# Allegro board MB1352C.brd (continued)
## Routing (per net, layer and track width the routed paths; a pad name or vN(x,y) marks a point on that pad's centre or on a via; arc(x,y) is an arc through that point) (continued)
NETCN4_3: length 38.4
  BOTTOM w0.155: SB63.1 41.96,44.78 41.96,47.77 31.87,57.86 18.19,57.86 17.6,57.28 16.38,57.28 15.57,58.09 15.57,59.72 16,60.15 16.49,60.15 CN4.3
NETCN6_13: length 14.6
  TOP w0.127: v1(10.79,38.86) 11.03,39.1 CN6.13 ; R20.2 v2(19.56,43.43)
  L3_SIG w0.102: v1(10.79,38.86) 11.1,39.17 12.14,39.17 16.92,43.94 19.05,43.94 v2(19.56,43.43)
NETCN6_14: length 14.6
  TOP w0.127: v1(10.79,39.88) 11.07,39.6 CN6.14 ; R15.2 v2(19.56,44.7)
  L3_SIG w0.102: v2(19.56,44.7) 19.18,44.32 16.76,44.32 11.98,39.55 11.13,39.55 v1(10.79,39.88)
NETCN6_19: length 3.9
  TOP w0.127: CN6.19 15.43,42.1 SB6.1
NETCN8_17: length 7
  BOTTOM w0.508: SB59.1 97.03,11.68 97.03,8.64 CN8.17
NETCN9_15: length 10
  BOTTOM w0.203: U7.1 44.2,11.05 SB24.2
  BOTTOM w0.508: SB24.2 43.81,11.68 42.55,12.95 36.83,12.95 CN9.15
NETD3_2: length 13.1
  BOTTOM w0.381: T10.3 28.63,10.85 ; T10.2 29.28,10.85
  BOTTOM w0.508: D8.2 29.88,8.89 ; D8.2 28.7,9.91 ; D8.2 28.7,7.87 ; 30.31,11.64 T10.1 29.93,10.97 ; 32.51,8.98 D3.2 ; D3.2 33.53,10.17 ; D3.2 31.5,10.17 ; D3.2 32.51,11.35 ; JP5.1 52.68,10.36 ; JP5.1 51.74,9.42 ; JP5.1 50.8,10.36
NETD7_2: length 18
  TOP w0.508: 106.17,14.61 U21.1 106.66,13.62 ; D7.2 112.07,15.75 ; D7.2 110.24,17.07 ; D7.2 108.41,15.75 ; D7.2 110.24,14.43 ; 104.3,20.82 L4.1 ; L4.1 110.17,20.82 ; L4.1 107.24,18.65 ; L4.1 107.24,23
NETD9_2: length 18.9
  TOP w0.508: 70.74,7.75 71.25,8.26 U22.1 ; D9.2 73.58,4.19 ; D9.2 72.26,2.36 ; D9.2 70.94,4.19 ; D9.2 72.26,6.02 ; L5.1 78.23,10.05 ; L5.1 78.23,4.18 ; L5.1 80.4,7.11 ; L5.1 76.05,7.11 ; 71.41,7.77 U22.1 ; U22.1 72.4,8.26
NETD11_1: length 2.1
  BOTTOM w0.127: D11.1 86.58,29.99 86.88,30.29 U10.1
NETD12_1: length 2
  TOP w0.127: D12.1 87.14,32.24 87.19,32.19 U14.1
NETLD1_1: length 1.5
  TOP w0.508: LD1.1 R125.1
NETLD2_1: length 1.5
  TOP w0.508: R10.1 LD2.1
NETR7_1: length 3.2
  TOP w0.508: R53.2 R54.2 R7.1
NETR7_2: length 5.5
  TOP w0.508: R7.2 89.28,20.6 88.65,21.23 v1(87.93,21.23)
  BOTTOM w0.508: v1(87.93,21.23) 87.93,19.13 88.39,18.67 SB3.2
NETR11_1: length 21.6
  TOP w0.127: 26.61,31.94 R36.2
  TOP w0.13: v2(23.04,46.25) 22.87,46.42 22.54,46.42 R11.1 ; U13.24 26.1,34.3 26.1,33.18 26.61,32.67 26.61,32.5 v2(26.44,32.33) 26.61,32.17 26.61,31.94
  BOTTOM w0.13: v2(23.04,46.25) 23.2,46.42 23.68,46.42 23.93,46.17 23.93,45.54 23.7,45.31 23.7,45.05 23.93,44.82 23.93,44.56 23.7,44.33 23.7,44.07 23.93,43.84 23.93,43.59 23.7,43.36 23.7,43.1 23.93,42.87 23.93,34.62 25.76,32.79 26.46,32.79 26.59,32.66 26.59,32.48 v2(26.44,32.33)
NETR12_1: length 21.7
  TOP w0.13: v2(23.04,46.96) 22.87,46.8 22.54,46.8 R12.1 ; R37.2 26.99,31.94 26.99,32.17 v2(27.15,32.33) 26.99,32.5 26.99,32.83 26.48,33.34 26.48,34.3 U13.25
  BOTTOM w0.13: v2(27.15,32.33) 26.97,32.51 26.97,32.82 26.62,33.17 25.91,33.17 24.31,34.78 24.31,46.33 23.84,46.8 23.2,46.8 v2(23.04,46.96)
NETR14_1: length 2.9
  TOP w0.127: U6.18 69.2,45.07 69.72,45.59 R14.1
NETR32_2: length 1.4
  BOTTOM w0.508: R75.1 R32.2
NETR33_2: length 9.1
  TOP w0.508: v1(92.84,31.11) 92.08,31.88 R34.2 91.51,32.19 U14.5 90.17,32.38 90.17,33.66 SB8.2 SB9.2
  BOTTOM w0.508: U10.5 91.76,30.29 R33.2 92.08,30.35 v1(92.84,31.11)
NETR41_1: length 1.2
  TOP w0.508: 31.88,27.51 R41.1 32.45,26.92
NETR43_2: length 2
  TOP w0.508: R43.2 v1(89.15,24.38)
  BOTTOM w0.508: v1(89.15,24.38) R43.2
NETR47_2: length 17.1
  TOP w0.508: R49.2 29.16,21.97 ; R49.2 27.79,21.97 ; R49.2 28.47,20.52 ; R49.2 28.47,23.42 ; 27.79,18.8 R56.2 ; R56.2 29.16,18.8 ; R56.2 28.47,20.24 ; R56.2 28.47,17.35 ; R47.2 28.47,17.07 ; R47.2 28.47,14.17 ; R47.2 29.16,15.62 ; R47.2 27.79,15.62 ; R52.2 29.16,12.45 ; R52.2 28.47,13.89 ; R52.2 28.47,11 ; R52.2 27.79,12.45
NETR48_2: length 17.1
  TOP w0.508: 44.5,28.7 R55.2 ; R55.2 45.87,28.7 ; R55.2 45.19,30.15 ; R55.2 45.19,27.25 ; R50.2 45.31,23.55 ; R50.2 44.63,22.1 ; R50.2 45.31,20.65 ; R50.2 46,22.1 ; 44.63,18.8 R48.2 ; R48.2 46,18.8 ; R48.2 45.31,20.24 ; R48.2 45.31,17.35 ; 45.19,23.95 R59.2 ; R59.2 45.19,26.85 ; R59.2 44.5,25.4 ; R59.2 45.87,25.4
NETR57_2: length 4
  TOP w0.381: R57.2 30.48,20.03 30.21,20.3 T8.3
  TOP w0.508: R57.2 30.61,19.18 30.61,17.65 30.23,17.27
NETR58_2: length 3.9
  TOP w0.508: v1(40.89,30.61) 40.51,30.23 R58.2 40.62,29.48 T9.3
  BOTTOM w0.508: SB36.2 40.44,30.15 v1(40.89,30.61)
NETR62_2: length 1.8
  TOP w0.508: U18.4 82.77,23.46 R62.2
NETR71_2: length 2.2
  TOP w0.508: R71.2 64.9,10.67 65.02,10.79 U22.6
NETR72_2: length 2.6
  BOTTOM w0.381: T10.4 27.98,11.9 27.69,12.19 27.18,12.19 26.29,13.08 26.16,13.08
NETR76_2: length 2.7
  TOP w0.508: R76.2 104.52,6.73 103.63,7.62 U21.6
NETR101_2: length 2.3
  TOP w0.508: U29.4 50.99,45.02 v1(50.93,44.96)
  BOTTOM w0.508: R101.2 50.93,44.32 v1(50.93,44.96)
NETR110_2: length 2.4
  TOP w0.508: v1(76.96,22.1) 76.96,22.35 77.22,22.61 U18.1
  BOTTOM w0.508: R110.2 76.96,22.86 v1(76.96,22.1)
NETR115_2: length 1.8
  BOTTOM w0.381: U27.4 51.45,25.71 51.27,25.53 R115.2
NETR116_2: length 4.7
  BOTTOM w0.508: U28.4 26.61,22.41 27.3,21.72 29.97,21.72 R116.2
NETR120_1: length 3.1
  BOTTOM w0.203: R120.1 SB24.1 44.81,9.91 U7.6
NETR121_1: length 27.7
  TOP w0.356: U24.1 43.67,9.54 43.46,9.75 42.93,9.75
  TOP w0.508: U26.1 v1(40.83,22.41) 40.64,22.61 38.99,22.61 37.72,21.34 35.69,21.34 34.92,20.57 34.92,11.94 35.81,11.05 37.47,11.05 38.77,9.75 42.93,9.75
  BOTTOM w0.508: R121.1 40.83,23.43 v1(40.83,22.41)
NETR121_2: length 2.5
  TOP w0.508: v1(42.55,22.48) 42.73,22.67 U26.4
  BOTTOM w0.508: R121.2 v1(42.55,22.48)
NETR122_1: length 17.2
  TOP w0.381: v1(21.08,2.54) 21.45,2.91 U23.1
  TOP w0.508: U25.1 19.37,15.05 v1(19.37,15.05)
  BOTTOM w0.508: v1(21.08,2.54) 20.83,2.54 18.67,4.7 18.67,14.35 v1(19.37,15.05) 19.81,15.49 R122.1
NETR122_2: length 2.6
  TOP w0.508: U25.4 21.27,15.94 21.72,15.49 v1(21.72,15.11)
  BOTTOM w0.508: R122.2 21.72,15.62 v1(21.72,15.11)
NETR126_1: length 2.6
  TOP w0.508: R126.1 16.03,9.93 16.38,10.29 SB25.1
NETSB7_2: length 3.6
  TOP w0.127: SB7.2 70.61,41.78 70.1,42.29 70.1,42.67 69.21,43.57 U6.15
NETSB10_2: length 4.3
  TOP w0.127: SB10.2 69.72,41.53 69.72,42.42 69.07,43.07 U6.14
NETSB11_2: length 1.5
  TOP w0.508: SB11.2 93.3,35.6 T3.1
NETSB12_2: length 1.8
  TOP w0.508: SB12.2 90.3,35.96 T2.1
NETSB16_2: length 3.3
  TOP w0.203: U16.7 96.75,55.39 v1(96.52,55.63) 96.39,55.75 SB16.2
  BOTTOM w0.203: v1(96.52,55.63) 96.39,55.75 SB16.2
NETSB17_2: length 4.1
  TOP w0.203: U16.6 97.28,55.79 v1(96.5,56.57) 95.67,57.4 SB17.2
  BOTTOM w0.203: SB17.2 95.67,57.4 v1(96.5,56.57)
NETSB18_1: length 4.5
  TOP w0.127: U13.21 24.89,33.78 24.07,32.96 23.43,32.96 22.99,32.51 22.99,32.26 SB18.1
NETSB19_1: length 3.7
  TOP w0.127: U13.22 25.29,33.42 24.26,32.39 24.26,32.13 SB19.1
NETSB20_1: length 3.3
  TOP w0.127: U13.23 25.69,33.06 24.89,32.26 SB20.1
NETSB21_1: length 2.1
  TOP w0.127: SB21.1 16.28,26.27 U17.12
NETSB22_1: length 2.2
  TOP w0.127: U17.11 16.68,26.2 SB22.1
NETSB26_2: length 14.6
  TOP w0.508: U18.3 79.76,22.61 81.41,20.95 84.45,20.95 85.72,22.23 90.04,22.23 v1(90.3,21.97)
  BOTTOM w0.508: SB26.2 90.32,20.55 90.32,21.95 v1(90.3,21.97)
NETSB27_2: length 3.7
  TOP w0.127: U17.6 17.66,22.57 v1(18.27,21.96) 18.51,21.72 SB27.2
  BOTTOM w0.127: v1(18.27,21.96) 18.51,21.72 SB27.2
NETSB28_2: length 3.6
  TOP w0.127: U17.7 17.8,22.97 18.03,22.73 v1(18.29,22.73) 18.67,23.11 SB28.2
  BOTTOM w0.127: v1(18.29,22.73) 18.67,23.11 SB28.2
NETSB33_2: length 2.7
  TOP w0.508: U21.3 103.63,14.13 105.16,15.65
NETSB37_2: length 2.1
  TOP w0.508: U22.3 72.26,10.79 72.9,10.16 SB37.2
NETSB48_1: length 4.7
  TOP w0.127: U13.32 28.81,36.21 29.72,35.31 29.72,35.18 v1(30.42,34.48)
  BOTTOM w0.127: 30.1,33.27 29.91,33.46 29.91,34.23 30.16,34.48 v1(30.42,34.48)
NETSB51_1: length 3.6
  TOP w0.127: U16.11 98.26,52.96 97.62,52.32 SB51.1
NETSB52_1: length 4.9
  TOP w0.127: U16.12 98.66,52.58 96.75,50.67 SB52.1
NETSB68_2: length 1.7
  TOP w0.155: SB68.2 101.43,55.79 U16.20
NETSB69_2: length 1.7
  TOP w0.155: SB69.2 101.43,55.39 U16.19
NETSB70_2: length 3.7
  TOP w0.155: U17.20 14.36,22.59 13.71,22.59 13.26,23.04 13.26,24 13.08,24.18 12.78,24.18 SB70.2
NETSB71_2: length 3.7
  TOP w0.155: SB71.2 12.8,24.56 13.23,24.56 13.64,24.16 13.64,23.2 13.87,22.97 U17.19
NETTP6_1: length 6.7
  TOP w0.127: U13.29 28.19,34.55 29.46,33.27 29.46,32.77 30.1,32.13 30.48,32.13 31.88,30.73 TP6.1
PORT1_CC1: length 62.2
  TOP w0.508: CN8.1 95.38,45.09 90.55,45.09 90.36,44.9 D10.1 90.36,42.87 89.92,42.42 SB4.1 89.92,39.35 T2.2 v1(88.27,38.8)
  BOTTOM w0.508: v1(88.27,38.8) 89.53,40.07 89.53,41.53 77.09,53.98 77.09,66.42 78.61,67.94 86.36,67.94 JP2.1
PORT1_CC2: length 49.2
  TOP w0.508: v1(91.95,38.8) T3.2 93.3,40.3 SB5.1 93.09,42.04 92.2,42.93 92.2,43.82 D10.3 92.45,44.07 96.9,44.07 CN8.2
  BOTTOM w0.508: JP1.1 79.5,66.42 78.36,65.28 78.36,54.36 83.44,49.28 85.6,49.28 90.55,44.32 90.55,40.19 v1(91.95,38.8)
PORT1_DB1: length 27.9
  BOTTOM w0.508: CN8.3 96.65,44.58 96.65,50.04 94.23,52.45 92.33,52.45 88.01,56.77 88.01,58.55 86.11,60.45 86.11,62.1 87.88,63.88
PORT1_DB2: length 32.8
  BOTTOM w0.508: 80.14,63.88 81.28,63.88 87,58.17 87,56.39 91.82,51.56 93.73,51.56 95.76,49.53 95.76,42.93 CN8.4
PORT2_CC1: length 53.4
  TOP w0.127: SB52.2 v1(93.09,49.78) 92.26,48.96 D10.4
  L3_SIG w0.102: v1(99.95,42.67) 101.55,41.07 102.9,41.07 103.3,40.67 103.3,37.39 99.85,33.93 99.85,19.08 CN8.13
  BOTTOM w0.127: SB44.2 100.46,43.18 v1(99.95,42.67) 99.31,42.04 99.31,39.75 98.93,39.37 97.06,39.37 94.61,41.81 94.61,48.26 v1(93.09,49.78)
PORT2_CC2: length 60.4
  TOP w0.127: D10.6 90.36,47.82 v1(92.33,49.78) 93.22,50.67 93.22,51.56 SB51.2
  L3_SIG w0.102: CN8.14 100.2,16.89 100.2,33.78 103.66,37.24 103.66,40.82 103.05,41.43 101.7,41.43 100.97,42.16 v1(100.97,42.54)
  BOTTOM w0.127: v1(92.33,49.78) 92.33,49.53 94.23,47.62 94.23,41.66 97.03,38.86 99.06,38.86 99.69,39.5 99.69,41.78 100.08,42.16 100.6,42.16 v1(100.97,42.54) 101.85,43.42 SB45.2
PSU: length 64
  TOP w0.508: 54.36,56.08 TP2.1 ; TP2.1 53.42,57.02 ; TP2.1 55.3,57.02 ; TP2.1 54.36,57.96 ; 107.62,1.98 C71.1 ; C71.1 106.86,3.43 ; C71.1 107.62,4.88 ; C71.1 108.38,3.43 ; SB33.1 v1(106.17,17.4) ; 77.98,15.54 C106.1 ; C106.1 77.98,16.71 ; C106.1 78.6,16.13 ; C107.1 78.6,17.53 ; C107.1 77.98,16.94 ; C107.1 77.98,18.11 ; 106.17,7.23 U21.8 106.66,8.22 ; 78,23.46 U18.2 ; U18.2 78.97,23.46 ; U18.2 78.49,21.97 ; C59.1 78.11,21.54 ; C59.1 78.73,20.95 ; C59.1 78.11,20.37 ; 80.06,18.41 R3.2 ; R3.2 81.23,18.41 ; R3.2 80.64,17.84 ; R125.2 47.62,57.91 ; C105.1 78.85,19.3 ; C105.1 78.11,20.12 ; C105.1 78.11,18.49 ; 49.91,53.72 52.63,53.72 ; 49.91,53.72 49.91,52.02 ; 49.91,53.72 49.91,55.42 ; L1.3 52.69,63.16 ; L1.3 51.52,61.99 ; L1.3 51.52,64.33 ; L1.3 50.35,63.16 ; 107.7,5.38 C65.1 ; C65.1 107.7,6.55 ; C65.1 107.07,5.97
  BOTTOM w0.508: 26.16,10.98 R72.1 ; R72.1 25.58,11.56 ; R72.1 26.75,11.56 ; v1(106.43,3.68) 106.43,17.14 v1(106.17,17.4) ; 24.18,11.56 R73.2 ; R73.2 25.35,11.56 ; R73.2 24.77,10.98 ; 24.9,7.87 D8.1 ; D8.1 23.72,8.89 ; D8.1 24.9,9.91 ; D8.1 26.08,8.89
  vias: v1(25.68,5.84) v1(25.65,5.08) v1(26.42,5.84) v1(26.42,5.08) v1(53.47,55.24) v1(53.47,54.36) v1(54.23,55.24) v1(54.23,54.36) v1(54.99,55.24) v1(54.99,54.36) v1(79.38,16.89) v1(79.38,16.13) v1(79.38,15.24) v1(80.14,16.89) v1(80.14,16.13) v1(80.14,15.24) v1(105.66,3.68) v1(105.66,2.79) v1(105.66,2.03) v1(106.43,2.79) v1(106.43,2.03)
PWD#: length 29
  TOP w0.127: U6.37 60.85,43.07 59.69,41.91 59.69,41.53 R25.1 v1(58.67,39.5)
  L3_SIG w0.102: CN9.6 40.01,38.99 57.4,38.99 57.91,39.5 v1(58.67,39.5)
PWM_CTL: length 4.6
  TOP w0.508: R61.1 R51.1 94.23,20.19 v1(95,19.43)
  BOTTOM w0.508: SB2.2 94.23,18.67 v1(95,19.43)
SOURCE_EN: length 65.3
  TOP w0.127: R124.2 54.61,37.85 v1(58.93,33.53)
  TOP w0.254: T5.3 49.04,37.48 R124.2
  L3_SIG w0.102: v1(58.93,33.53) 59.69,32.77 82.55,32.77 85.22,30.1 85.22,27.46 88.93,23.75 88.93,18.72 90.88,16.76 93.09,16.76 97.41,12.45 CN8.15
SSEQ0_A0: length 4.6
  TOP w0.127: v1(22.91,40.01) 22.94,40.01 23.06,39.88 23.06,39.5 23.95,38.61 U13.11
  BOTTOM w0.127: R93.2 R95.1 22.73,40.01 v1(22.91,40.01)
SSEQ1: length 5.3
  TOP w0.127: R19.1 28.57,42.67 28.57,42.42 v1(28.38,42.23) 28.19,42.04 28.07,42.04 26.89,40.86 U13.3
  BOTTOM w0.127: v1(28.38,42.23) 28.57,42.42 28.57,42.67 R19.1
SSRX+: length 25.3
  TOP w0.155: C21.1 26.99,45.15 26.99,48.04 25.12,49.91 16.64,49.91 16.18,50.37 16.18,50.92 v1(15.96,51.14) 16.18,51.35 16.18,52.49 16.12,52.55 U4.4
  BOTTOM w0.155: CN4.6 18.94,55.98 18.94,55.16 16.18,52.41 16.18,51.35 v1(15.96,51.14)
SSRX-: length 25.3
  TOP w0.155: C22.1 27.37,45.15 27.37,48.2 25.27,50.29 16.79,50.29 16.56,50.53 16.56,50.92 v1(16.78,51.14) 16.56,51.35 16.56,52.49 16.62,52.55 U4.5
  BOTTOM w0.155: v1(16.78,51.14) 16.56,51.35 16.56,52.25 19.32,55.01 19.32,55.98 CN4.5
SSTX+: length 22.9
  TOP w0.155: U4.1 14.62,52.94 14.68,52.88 14.68,52.24 v1(14.46,52.03) 14.68,51.81 14.68,50.06 15.97,48.77 22.96,48.77 24.32,47.4 24.32,45.15 C19.1
  BOTTOM w0.155: v1(14.46,52.03) 14.68,52.24 14.68,52.85 12.19,55.35 12.19,55.98 CN4.9
SSTX-: length 22.9
  TOP w0.155: C20.1 24.7,45.15 24.7,47.56 23.11,49.15 16.13,49.15 15.06,50.22 15.06,51.81 v1(15.28,52.03) 15.06,52.24 15.06,52.91 15.12,52.97 U4.2
  BOTTOM w0.155: v1(15.28,52.03) 15.06,52.24 15.06,53.01 12.57,55.5 12.57,55.98 CN4.8
SW_EN: length 5.3
  TOP w0.127: R29.1 R28.2 82.92,36.71 U8.J5
USB3_DET: length 21.1
  TOP w0.508: R1.2 R2.1 32.26,56.39 34.54,54.1 34.54,47.24 CN9.2
V_CTL1: length 6.3
  BOTTOM w0.508: CN8.12 98.17,20.19 SB2.1 SB14.1
V_CTL2: length 74.5
  L3_SIG w0.102: v1(53.61,40.64) 53.48,40.51 50.04,40.51 49.15,41.4 48.13,41.4 47.36,40.62 40.91,40.62 37.47,44.07 37.47,46.86 CN9.1
  BOTTOM w0.127: SB23.1 SB15.1 91.19,22.86 91.19,25.02 91.06,25.15 87.5,25.15 84.2,28.45 84.2,32.1 83.54,32.77 71.85,32.77 69.82,34.8 58.9,34.8 53.61,40.09 v1(53.61,40.64)
VCONN_EN1: length 19.2
  TOP w0.508: SB12.1 v1(87.25,35.43) ; CN8.6 95.76,32.77 v1(93.85,32.77)
  L3_SIG w0.508: v1(87.25,35.43) 87.63,35.05 91.57,35.05 v1(93.85,32.77)
  BOTTOM w0.508: U10.4 91.51,32.19 R33.1 R9.1 v1(93.85,32.77)
VCONN_EN2: length 18.5
  TOP w0.508: v1(91.57,36.58) 91.95,36.2 SB11.1 ; U14.4 91.76,30.29 R34.1 R8.2 v1(94.74,30.35) 95.89,30.35 CN8.7
  L3_SIG w0.508: v1(94.74,30.35) 95.63,31.24 95.63,32.51 v1(91.57,36.58)
VCONN_OUT: length 90.6
  TOP w0.508: 109.8,33.15 TP5.1 ; TP5.1 110.74,34.09 ; TP5.1 111.68,33.15 ; TP5.1 110.74,32.21 ; SB9.1 94.49,33.78 94.74,34.04 v1(95.76,34.04) ; 105.54,34.14 C45.1 ; C45.1 106.3,35.59 ; C45.1 106.3,32.69 ; C45.1 107.06,34.14 ; L4.2 110.17,29.72 ; L4.2 104.3,29.72 ; L4.2 107.24,27.55 ; L4.2 107.24,31.9 ; v1(103.25,6.86) 103.12,6.73 C74.1
  BOTTOM w0.508: JP3.1 85.22,52.58 93.6,44.2 93.6,40.77 95.5,38.86 95.5,34.29 v1(95.76,34.04) 99.57,34.04 100.58,35.05 102.87,35.05 103.38,35.56 v1(105.16,35.56) 105.13,35.53 105.13,9.63 103.17,7.66 103.17,6.94 v1(103.25,6.86) 103.38,6.73 103.89,6.73 104.52,6.1 R75.2
VDC: length 30
  TOP w0.508: 58.37,7.19 C66.1 ; C66.1 61.27,7.19 ; C66.1 59.82,7.95 ; C66.1 59.82,6.43 ; v1(74.8,9.02) 74.8,10.03 ; C67.1 62.81,6.35 ; C67.1 61.65,6.35 ; C67.1 62.23,6.97 ; 65.02,8.26 U22.8 66.01,7.77
  BOTTOM w0.508: v1(74.8,9.02) 58.93,9.02 v1(57.78,7.87) ; JP5.2 52.68,12.9 ; JP5.2 51.74,11.96 ; JP5.2 50.8,12.9 ; JP5.2 51.74,13.84
  vias: v1(56.9,7.87) v1(56.9,6.99) v1(56.9,6.22) v1(57.78,6.99) v1(57.78,6.22)
VSENSE_1: length 11
  BOTTOM w0.508: U28.1 28.57,20.57 R116.1 31.62,20.57 32.89,21.84 32.89,24 34.04,25.15 CN9.10
VSENSE_2: length 21.7
  BOTTOM w0.508: CN9.12 39.75,23.5 39.75,24.13 40.26,24.64 46.74,24.64 47.37,24 R115.1 50.93,24 51.56,24.64 53.72,24.64 54.16,24.2 U27.1
VSENSE_DCDC: length 62.9
  TOP w0.127: U29.1 41.85,43.89 40.01,42.04 v1(40.01,37.97)
  TOP w0.508: U29.1 v1(49.09,44.96)
  L3_SIG w0.102: v1(40.01,37.97) 40.01,35.18 42.93,32.26 52.83,32.26 54.61,30.48 v1(54.61,17.02)
  BOTTOM w0.127: v1(54.61,17.02) 50.16,17.02 48.51,15.37 48.51,10.79 47.88,10.16 46.12,10.16 U7.4
  BOTTOM w0.508: R101.1 49.09,44.13 v1(49.09,44.96)
VSOURCE: length 65.8
  TOP w0.381: 49.83,33.6 49.83,33.6 T7.7 ; T7.6 49.86,32.95
  TOP w0.508: 49.06,34.63 T7.8 49.74,34.25 ; C52.1 63.5,18.97 ; C52.1 62.75,18.16 ; C52.1 63.5,17.35 ; 49.06,31.92 T7.5 49.74,32.3 ; C53.1 61.94,23.65 ; C53.1 63.67,22.73 ; C53.1 60.21,22.73 ; C53.1 61.94,21.82 ; L2.2 62.32,34.91 ; L2.2 63.71,30.73 ; L2.2 60.94,30.73 ; L2.2 62.32,26.56 ; R83.2 v1(52.58,38.48)
  BOTTOM w0.508: v1(52.58,38.48) v1(52.58,34.42) ; 63.42,19.94 C104.1 ; C104.1 63.88,20.4 ; C104.1 63.88,19.48 ; R45.2 R127.2 81.41,31.25 72.78,31.25 67.82,26.29 59.56,26.29 58.17,24.89 v1(58.17,22.73) ; 62.84,20.65 R60.2 ; R60.2 62.15,22.1 ; R60.2 62.84,23.55 ; R60.2 63.53,22.1 ; C103.1 63.88,19.25 ; C103.1 63.88,18.34 ; C103.1 63.42,18.8
  vias: v1(60.58,19.3) v1(60.58,18.41) v1(60.58,17.53) v1(61.47,19.3) v1(61.47,18.41) v1(61.47,17.53)
VSOURCE_9V: length 3.7
  TOP w0.508: v1(94.87,23.37) R44.1 R46.2
  BOTTOM w0.508: R44.1 v1(94.87,23.37)
VSOURCE_15V: length 3.8
  TOP w0.508: v1(92.2,24.51) R44.2 R43.1
  BOTTOM w0.508: v1(92.2,24.51) R44.2

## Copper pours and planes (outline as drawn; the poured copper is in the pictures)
+3V3 on BOTTOM (solid shape): 72.42,57.4 71.91,56.9 70.99,56.9 70.99,57.91 71.91,57.91
+3V3 on BOTTOM (solid shape): 14.44,43.3 14.95,42.8 13.59,42.8 13.59,43.81 14.95,43.81
+3V3 on L3_SIG: 17.14,12.06 19.94,14.86 19.94,18.8 21.21,20.07 23.75,20.07 25.02,21.34 33.53,21.34 34.54,22.35 37.97,22.35 38.8,23.18 38.8,28.26 39.62,29.08 54.23,29.08 54.74,28.57 54.74,13.46 52.2,10.92 50.93,10.92 49.02,9.02 45.21,9.02 43.31,10.92 38.23,10.92 37.72,10.41 27.18,10.41 24.89,8.13 24.89,5.21 23.5,3.81 17.65,3.81 17.14,4.32
D5V on TOP (solid shape): 89.12,33.78 89.63,33.27 88.27,33.27 88.27,34.29 89.63,34.29
D5V on TOP: 93.62,11.92 93.85,11.68 95.94,11.68 96.52,11.1 99.01,11.1 99.44,10.67 99.44,9.02 98.98,8.56 96.77,8.56 94.74,6.53 94.74,5.59 93.98,4.83 89.92,4.83 88.65,3.56 88.65,2.41 88.27,2.03 83.95,2.03 83.31,2.67 83.31,11.48 83.75,11.92
GND on TOP (solid shape): 18.67,42.8 17.75,42.8 17.24,43.31 17.75,43.81 18.67,43.81
GND on TOP (solid shape): 21.46,22.61 20.1,22.61 20.61,23.11 20.1,23.62 21.46,23.62
GND on TOP (solid shape): 21.46,21.21 20.1,21.21 20.61,21.71 20.1,22.23 21.46,22.23
GND on TOP (solid shape): 73.66,54.48 72.64,54.48 72.64,55.84 73.15,55.34 73.66,55.85
GND on TOP (solid shape): 94.33,57.41 94.84,56.9 93.47,56.9 93.47,57.91 94.83,57.91
GND on TOP (solid shape): 94.33,55.76 94.84,55.24 93.47,55.24 93.47,56.26 94.83,56.26
GND on TOP: 38.23,51.18 38.23,55.88 38.99,56.64 45.47,56.64 45.85,56.26 45.85,50.55 45.63,50.33 39.08,50.33
GND on TOP: 100.71,36.2 103.94,36.2 104.39,35.74 104.39,32.51 104.01,32.13 100.58,32.13 100.33,32.38 100.33,35.81
GND on TOP: 76.83,15.49 76.58,15.24 74.93,15.24 73.79,16.38 65.41,16.38 64.77,17.02 64.77,24.38 65.53,25.15 74.68,25.15 76.83,27.3 77.72,27.3 77.98,27.56 82.3,27.56 82.55,27.3 82.55,24.64 82.42,24.51 76.71,24.51 76.07,23.88 76.07,21.21 76.45,20.83 76.71,20.83 76.83,20.7
GND on TOP: 102.36,12.32 106.3,12.32 106.55,12.06 106.55,9.78 106.3,9.53 102.36,9.53 102.11,9.78 102.11,12.06
GND on TOP: 69.47,1.27 56.77,1.27 56.39,1.65 56.39,4.95 56.64,5.21 63.37,5.21 63.5,5.33 63.5,6.1 63.75,6.35 69.47,6.35 69.98,5.84 69.98,1.78
GND on TOP: 112.65,12.06 113.03,11.68 113.03,1.78 112.52,1.27 109.73,1.27 109.35,1.65 109.35,4.83 108.84,5.33 108.84,6.48 107.82,7.49 107.82,11.81 108.08,12.06
GND on TOP: 67.44,12.19 69.98,12.19 70.1,12.06 70.1,8.13 69.98,8 67.44,8 67.31,8.13 67.31,12.06
GND on TOP: 93.34,3.94 89.79,3.94 89.28,3.43 89.28,0.89 89.53,0.64 93.34,0.64 93.6,0.89 93.6,3.68
GND on TOP: 30.86,21.08 33.02,21.08 33.4,20.7 33.4,18.67 33.02,18.29 31.62,18.29 31.5,18.41 31.5,19.56 30.86,20.19
GND on BOTTOM: 65.15,24 68.96,24 69.22,23.75 69.22,16.89 68.96,16.64 65.15,16.64 64.64,17.14 64.64,23.5
GND on L2_GND, L5_GND: 0.51,0.51 0.51,73.15 113.79,73.15 113.79,0.51
GND on L3_SIG: 0.76,22.23 0.64,22.35 0.64,73.03 113.41,73.03 113.67,72.77 113.67,50.16 111.63,48.13 99.57,48.13 98.93,47.5 87,47.5 86.11,46.61 86.11,46.23 85.85,45.97 84.96,45.97 84.07,46.86 84.07,50.29 84.2,50.42 84.71,50.42 85.09,50.8 85.09,52.32 84.84,52.58 82.8,52.58 81.92,51.69 81.92,46.86 81.66,46.61 76.45,46.61 73.79,43.94 64.01,43.94 61.47,41.4 57.53,41.4 56.13,40.01 40.77,40.01 36.96,43.81 35.18,43.81 33.27,41.91 29.97,41.91 29.21,41.15 29.21,35.94 28.19,34.92 23.24,34.92 17.27,28.96 11.3,28.96 8.13,25.78 8.13,22.48 7.87,22.23 ; 2 cut-outs
GND on L3_SIG: 73.53,0.64 75.18,2.29 75.18,17.65 76.26,18.73 81.6,18.73 84.84,15.49 84.84,12.57 86.11,11.3 94.11,11.3 94.49,11.68 94.49,14.86 92.96,16.38 90.81,16.38 88.65,18.54 88.65,23.5 84.96,27.18 84.96,29.84 82.68,32.13 59.44,32.13 57.91,30.61 57.91,9.78 51.69,3.56 43.69,3.56 43.18,4.06 43.18,9.65 42.55,10.29 38.86,10.29 38.1,9.53 27.3,9.53 25.65,7.87 25.65,4.83 24.13,3.3 17.53,3.3 16.76,4.06 16.76,6.1 16,6.86 11.18,6.86 9.65,5.33 9.65,4.83 8.76,2.6 8.76,1.78 9.91,0.64
GND on L3_SIG: 113.67,1.14 113.28,0.76 109.6,0.76 109.22,1.14 109.22,3.17 109.35,3.3 109.35,14.22 108.2,15.37 101.88,15.37 100.85,16.4 100.85,34.05 101.41,34.61 107.63,34.61 108.13,35.1 111.38,35.1 113.67,32.82
VBUS1 on TOP (solid shape): 16.89,12.67 16.38,12.16 15.88,12.67 15.88,13.59 16.89,13.59
VBUS1 on TOP: 21.46,6.6 21.31,6.45 17.55,6.45 17.27,6.73 17.27,10.92 17.53,11.18 21.21,11.18 21.46,10.92
VBUS1 on L4_VCC: 0.51,0.51 0.51,23.62 18.06,23.62 18.8,22.88 18.8,0.51
VBUS2 on TOP: 39.88,12.06 39.62,12.32 39.62,17.02 40.13,17.53 43.18,17.53 43.56,17.14 43.56,12.32 43.31,12.06
VBUS2 on L4_VCC: 40.39,20.07 40.89,20.57 49.15,20.57 58.17,11.56 97.64,11.56 100.46,14.37 100.46,46.38 101.96,47.88 113.79,47.88 113.79,0.51 40.99,0.51 40.39,1.12
VDD on BOTTOM (solid shape): 94.9,13.21 94.39,12.7 93.47,12.7 93.47,13.72 94.39,13.72
VDD on BOTTOM: 98.81,3.17 99.44,3.81 99.44,5.59 98.81,6.22 95.38,6.22 93.34,8.26 93.34,10.16 93.73,10.54 93.73,12.45 94.3,13.02 94.3,13.53 93.47,14.35 89.41,14.35 89.15,14.1 89.15,8.38 90.74,6.79 90.74,5.27 92.84,3.17
VDD on L4_VCC: 19.3,23.09 18.27,24.13 0.51,24.13 0.51,73.15 113.79,73.15 113.79,48.39 101.75,48.39 99.95,46.59 99.95,14.58 97.43,12.06 87.63,12.06 87.63,21.97 80.39,29.21 63.1,29.21 55.63,36.68 55.63,48.41 58.04,50.82 58.04,58.02 56.49,59.56 39.9,59.56 38.48,58.14 38.48,30.6 28.08,20.19 28.08,14.86 23.75,10.53 23.75,5.59 25.15,4.19 27.05,4.19 27.81,4.95 27.81,7.37 28.83,8.38 39.12,8.38 39.88,7.62 39.88,1.27 39.12,0.51 19.43,0.51 19.3,0.64
1_CC1 on TOP (solid shape): 16.26,27.91 15.75,27.4 15.24,27.91 15.24,28.83 16.26,28.83
1_CC1 on TOP (solid shape): 89.31,40.51 88.8,40.01 87.88,40.01 87.88,41.02 88.8,41.02
1_CC1 on BOTTOM (solid shape): 16.89,14.07 16.38,13.56 15.88,14.07 15.88,14.99 16.89,14.99
1_CC2 on TOP (solid shape): 17.78,27.91 17.27,27.4 16.76,27.91 16.76,28.83 17.78,28.83
1_CC2 on TOP (solid shape): 92.49,40.51 91.98,40.01 91.06,40.01 91.06,41.02 91.98,41.02
1_CC2 on BOTTOM (solid shape): 17.02,17.62 16.51,17.11 16,17.62 16,18.54 17.02,18.54
1_SBU1 on BOTTOM (solid shape): 13.97,14.07 13.46,13.56 12.95,14.07 12.95,14.99 13.97,14.99
1_SBU2 on BOTTOM (solid shape): 15.49,15.49 14.57,15.49 14.07,16 14.57,16.51 15.49,16.51
2_SBU1 on TOP (solid shape): 102.87,48.61 102.36,48.1 101.85,48.61 101.85,49.53 102.87,49.53
2_SBU2 on TOP (solid shape): 101.47,48.61 100.97,48.1 100.46,48.61 100.46,49.53 101.47,49.53
C1_CC1 on BOTTOM (solid shape): 16.39,13.3 16.89,13.81 16.89,12.45 15.88,12.45 15.88,13.81
C1_CC1 on BOTTOM (solid shape): 21.46,22.61 20.1,22.61 20.61,23.12 20.1,23.62 21.46,23.62
C1_CC2 on BOTTOM (solid shape): 16.51,16.86 17.02,17.36 17.02,16 16,16 16,17.37
C1_CC2 on BOTTOM (solid shape): 21.46,21.21 20.1,21.21 20.61,21.72 20.1,22.23 21.46,22.23
C1_D+ on TOP (solid shape): 11.02,25.17 11.53,24.66 10.16,24.66 10.16,25.68 11.52,25.68
C1_D+ on BOTTOM (solid shape): 41.88,43.08 41.88,42.16 40.87,42.16 40.87,43.08 41.38,43.59
C1_D+ on BOTTOM (solid shape): 41.88,40.23 41.38,39.72 40.87,40.23 40.87,41.15 41.88,41.15
C1_D- on TOP (solid shape): 11.02,23.6 11.53,23.09 10.16,23.09 10.16,24.1 11.52,24.1
C1_D- on BOTTOM (solid shape): 43.46,43.08 43.46,42.16 42.44,42.16 42.44,43.08 42.95,43.59
C1_D- on BOTTOM (solid shape): 43.46,40.23 42.95,39.72 42.44,40.23 42.44,41.15 43.46,41.15
C1_SBU1 on BOTTOM (solid shape): 13.46,13.3 13.97,13.81 13.97,12.45 12.95,12.45 12.95,13.81
C1_SBU2 on BOTTOM (solid shape): 13.81,16 14.32,15.49 12.95,15.49 12.95,16.51 14.32,16.51
C2_CC1 on BOTTOM (solid shape): 94.33,55.75 94.83,55.24 93.47,55.24 93.47,56.26 94.84,56.26
C2_CC1 on BOTTOM (solid shape): 100.97,44.35 100.45,44.86 99.95,44.36 99.95,45.72 100.97,45.72
C2_CC2 on BOTTOM (solid shape): 94.33,57.4 94.83,56.9 93.47,56.9 93.47,57.91 94.84,57.91
C2_CC2 on BOTTOM (solid shape): 102.36,44.35 101.85,44.86 101.35,44.36 101.35,45.72 102.36,45.72
C2_D+ on TOP (solid shape): 87.76,51.71 86.4,51.71 86.9,52.22 86.39,52.73 87.76,52.73
C2_D+ on TOP (solid shape): 89.63,52.22 90.14,51.71 88.77,51.71 88.77,52.73 90.13,52.73
C2_D+ on TOP (solid shape): 104.04,54.31 102.68,54.31 103.18,54.81 102.67,55.32 104.04,55.32
C2_D- on TOP (solid shape): 87.76,50.14 86.4,50.14 86.9,50.65 86.39,51.16 87.76,51.16
C2_D- on TOP (solid shape): 89.63,50.68 90.14,50.16 88.77,50.16 88.77,51.18 90.13,51.18
C2_D- on TOP (solid shape): 104.04,55.85 102.68,55.85 103.18,56.36 102.67,56.87 104.04,56.87
C2_SBU1 on TOP (solid shape): 102.87,46.99 101.85,46.99 101.85,48.35 102.36,47.85 102.87,48.36
C2_SBU2 on TOP (solid shape): 101.47,46.99 100.46,46.99 100.46,48.35 100.96,47.85 101.47,48.36
CON1_D+ on BOTTOM (solid shape): 41.38,39.46 41.88,39.97 41.88,38.61 40.87,38.61 40.87,39.97
CON1_D- on BOTTOM (solid shape): 42.95,39.46 43.46,39.97 43.46,38.61 42.44,38.61 42.44,39.97
CON2_D+ on TOP (solid shape): 86.65,52.22 86.14,51.71 85.22,51.71 85.22,52.73 86.14,52.73
CON2_D- on TOP (solid shape): 86.65,50.65 86.14,50.14 85.22,50.14 85.22,51.16 86.14,51.16
DCDC_EN on BOTTOM (solid shape): 92.71,19.08 92.71,18.16 91.69,18.16 91.69,19.08 92.2,19.59
DCDC_EN on BOTTOM (solid shape): 90.68,19.02 91.19,19.52 91.19,18.16 90.17,18.16 90.17,19.53
DISCHARGE_1 on TOP (solid shape): 32.51,16.89 31.15,16.89 31.66,17.4 31.15,17.91 32.51,17.91
DISCHARGE_2 on BOTTOM (solid shape): 40.44,28.36 40.95,28.87 40.95,27.51 39.93,27.51 39.93,28.87
DP_PWR_SINK on BOTTOM (solid shape): 16.13,42.8 15.21,42.8 14.7,43.31 15.21,43.81 16.13,43.81
DP_PWR_SOURCE on BOTTOM (solid shape): 73.53,56.9 72.17,56.9 72.68,57.41 72.17,57.91 73.53,57.91
HPDIN on TOP (solid shape): 25.4,30.26 25.4,29.34 24.38,29.34 24.38,30.26 24.89,30.77
HPDIN on BOTTOM (solid shape): 30.35,32.42 30.35,31.5 29.34,31.5 29.34,32.42 29.84,32.92
I2C_SCL on TOP (solid shape): 22.61,30.26 22.61,29.34 21.59,29.34 21.59,30.26 22.1,30.77
I2C_SCL on TOP (solid shape): 72.9,41.27 71.54,41.27 72.04,41.78 71.53,42.29 72.9,42.29
I2C_SDA on TOP (solid shape): 24,30.26 24,29.34 22.99,29.34 22.99,30.26 23.5,30.77
I2C_SDA on TOP (solid shape): 72.9,39.88 71.54,39.88 72.04,40.38 71.53,40.89 72.9,40.89
LOCAL_PWR1 on TOP (solid shape): 27.36,24.64 25.63,24.64 25.63,26.9 27.36,26.9
LOCAL_PWR1 on BOTTOM (solid shape): 30.07,12.78 27.84,12.78 27.84,14.5 30.07,14.5
LOCAL_PWR1 on TOP: 27.56,27.18 27.56,24.38 26.73,23.56 26.73,10.73 27.43,10.03 27.43,6.73 27.05,6.35 23.5,6.35 23.24,6.6 23.24,21.72 22.48,22.48 22.48,25.4 24.51,27.43 27.3,27.43
LOCAL_PWR1 on BOTTOM: 34.29,13.21 33.91,12.83 27.43,12.83 27.05,13.21 27.05,13.97 26.8,14.22 23.62,14.22 23.24,14.61 23.24,16.64 23.62,17.02 33.91,17.02 34.29,16.64
LOCAL_PWR2 on TOP: 45.97,12.06 45.72,12.32 45.72,16.26 46.23,16.76 46.99,16.76 47.24,17.02 47.24,30.35 47.5,30.61 49.02,30.61 49.28,30.35 49.28,24.38 49.59,24.07 53.53,24.07 54.36,23.24 54.36,4.32 51.69,1.65 33.53,1.65 32.77,2.41 28.51,2.41 28,2.92 28,6.29 28.7,6.99 47.62,6.99 50.1,9.46 50.1,20 49.91,20.19 49.4,20.19 49.28,20.07 49.28,12.45 48.9,12.06
NETC1_1 on TOP: 38.38,60.45 42.16,60.45 43.81,62.1 43.81,65.15 43.31,65.66 37.59,65.66 37.29,65.35 37.29,63.75 36.92,63.39 33.63,63.39 32.88,62.64 29.69,62.64 28.91,63.42 27.43,63.42 27.08,63.07 27.08,59.89 29.18,57.78 35.71,57.78
NETC1_2 on TOP: 44.98,66.49 45.67,67.18 47.12,67.18 48.01,68.07 48.01,69.85 47.37,70.48 38.23,70.48 37.34,69.6 29.79,69.6 29.34,69.14 29.34,63.83 29.84,63.32 32.56,63.32 33.08,63.84 33.08,65.53 34.04,66.49
NETC4_1 on TOP: 37.49,23.77 33.25,23.77 33.02,24 29.72,24 29.46,24.26 29.46,26.16 29.59,26.29 34.8,26.29 35.69,27.18 35.69,31.62 36.83,32.77 37.97,32.77 40.13,34.92 45.21,34.92 45.34,34.8 45.34,32.77 45.21,32.64 41.78,32.64 39.5,30.35 39.5,25.78
NETC56_2 on TOP: 65.91,34.67 66.42,35.18 74.74,35.18 76.36,33.56 76.36,31.37 76.61,31.11 77.6,31.11 77.72,30.99 77.72,27.69 77.6,27.56 76.07,27.56 74.42,25.91 66.17,25.91 65.91,26.16
NETC58_1 on TOP: 100.46,5.46 99.95,5.97 99.95,16.51 100.08,16.64 102.62,16.64 102.74,16.51 102.74,15.37 101.85,14.48 101.85,9.27 102.11,9.02 102.62,9.02 102.74,8.89 102.74,6.99 102.49,6.73 102.49,5.71 102.23,5.46
NETC61_1 on TOP: 63.63,15.24 73.53,15.24 73.66,15.11 73.66,12.7 67.18,12.7 66.93,12.45 66.93,11.94 66.8,11.81 65.15,11.81 64.64,11.3 63.63,11.3 63.37,11.56 63.37,14.99
NETC109_2 on BOTTOM (solid shape): 89.16,22.19 89.66,22.7 89.66,21.34 88.65,21.34 88.65,22.7
NETC109_2 on BOTTOM (solid shape): 89.66,19.34 89.15,19.85 88.65,19.34 88.65,20.7 89.66,20.7
NETCN1_2 on TOP (solid shape): 91.31,50.16 90.39,50.16 89.88,50.67 90.39,51.18 91.31,51.18
NETCN1_3 on TOP (solid shape): 91.31,51.71 90.39,51.71 89.88,52.22 90.39,52.73 91.31,52.73
NETCN2_19 on TOP (solid shape): 73.66,56.1 73.15,55.59 72.64,56.1 72.64,57.02 73.66,57.02
NETCN4_2 on BOTTOM (solid shape): 43.46,43.34 42.95,43.85 42.44,43.34 42.44,44.7 43.46,44.7
NETCN4_3 on BOTTOM (solid shape): 41.88,43.34 41.37,43.85 40.87,43.34 40.87,44.7 41.88,44.7
NETCN6_19 on TOP (solid shape): 16.98,43.31 17.49,42.8 16.13,42.8 16.13,43.81 17.49,43.81
NETCN8_17 on BOTTOM (solid shape): 96.01,12.7 94.65,12.7 95.16,13.21 94.65,13.72 96.01,13.72
NETCN9_15 on BOTTOM (solid shape): 44.32,11.02 43.81,10.51 43.31,11.02 43.31,11.94 44.32,11.94
NETD3_2 on BOTTOM: 49.53,11.05 54.1,11.05 55.12,10.03 55.12,1.65 53.98,0.51 28.19,0.51 27.69,1.02 27.69,10.29 28.45,11.05 28.45,12.06 28.57,12.19 33.15,12.19 34.67,10.67 34.67,4.19 35.31,3.56 46.99,3.56 47.75,4.32 47.75,9.27
NETD7_2 on TOP: 106.05,12.83 112.52,12.83 112.78,13.08 112.78,23.88 112.52,24.13 102.11,24.13 101.73,23.75 101.73,18.8 102.11,18.41 106.05,18.41 106.68,17.78 106.68,15.62 105.92,14.86 105.92,13.21 105.79,13.08
NETD9_2 on TOP: 70.87,1.78 80.64,1.78 81.28,2.41 81.28,10.92 80.52,11.68 76.45,11.68 75.82,11.05 75.82,9.02 75.31,8.51 70.61,8.51 70.48,8.38 70.48,2.16
NETR7_2 on BOTTOM (solid shape): 89.66,19.08 89.66,18.16 88.65,18.16 88.65,19.08 89.15,19.59
NETR33_2 on TOP (solid shape): 90.81,33.27 89.88,33.27 89.38,33.78 89.88,34.29 90.81,34.29
NETR33_2 on TOP (solid shape): 92.87,33.78 92.36,33.27 91.44,33.27 91.44,34.29 92.36,34.29
NETR41_1 on TOP: 34.92,27.56 33.66,26.29 31.62,26.29 31.5,26.42 31.5,28.07 32.89,29.46 32.89,34.29 35.56,36.96 48.39,36.96 48.51,36.83 48.51,36.07 48.39,35.94 44.83,35.94 44.26,35.37 39.31,35.37 37.53,33.59 36.39,33.59 34.92,32.13
NETR43_2 on BOTTOM (solid shape): 89.66,22.96 89.15,22.45 88.65,22.96 88.65,23.88 89.66,23.88
NETR47_2 on TOP: 29.84,21.41 29.59,21.16 29.59,10.92 29.21,10.54 27.81,10.54 27.37,10.99 27.37,23.43 27.94,24 29.02,24 29.46,23.56 32.83,23.56 33.02,23.37 33.02,21.72 32.72,21.41
NETR48_2 on TOP: 45.85,17.02 44.32,17.02 43.81,17.53 43.81,26.42 43.56,26.67 42.67,26.67 42.42,26.92 42.42,30.1 42.8,30.48 46.1,30.48 46.35,30.23 46.35,17.53
NETR57_2 on TOP (solid shape): 31.4,17.4 30.89,16.89 29.97,16.89 29.97,17.91 30.89,17.91
NETR58_2 on BOTTOM (solid shape): 40.95,29.13 40.44,28.62 39.93,29.13 39.93,30.05 40.95,30.05
NETR120_1 on BOTTOM (solid shape): 43.82,10.25 44.32,10.76 44.32,9.4 43.31,9.4 43.31,10.76
NETR126_1 on TOP (solid shape): 16.89,11.05 15.88,11.05 15.88,12.41 16.38,11.9 16.89,12.41
NETSB7_2 on TOP (solid shape): 71.79,41.78 71.28,41.27 70.36,41.27 70.36,42.29 71.28,42.29
NETSB10_2 on TOP (solid shape): 71.79,40.39 71.28,39.88 70.36,39.88 70.36,40.89 71.28,40.89
NETSB11_2 on TOP (solid shape): 93.98,34.92 93.06,34.92 92.55,35.43 93.06,35.94 93.98,35.94
NETSB12_2 on TOP (solid shape): 90.81,34.92 89.88,34.92 89.38,35.43 89.88,35.94 90.81,35.94
NETSB16_2 on TOP (solid shape): 96.01,55.24 95.09,55.24 94.58,55.75 95.09,56.26 96.01,56.26
NETSB16_2 on BOTTOM (solid shape): 96.01,55.24 95.09,55.24 94.58,55.75 95.09,56.26 96.01,56.26
NETSB17_2 on TOP (solid shape): 96.01,56.9 95.09,56.9 94.58,57.4 95.09,57.91 96.01,57.91
NETSB17_2 on BOTTOM (solid shape): 96.01,56.9 95.09,56.9 94.58,57.4 95.09,57.91 96.01,57.91
NETSB18_1 on TOP (solid shape): 22.61,30.52 22.1,31.02 21.59,30.51 21.59,31.88 22.61,31.88
NETSB19_1 on TOP (solid shape): 24,30.52 23.5,31.02 22.99,30.51 22.99,31.88 24,31.88
NETSB20_1 on TOP (solid shape): 25.4,30.52 24.89,31.02 24.38,30.51 24.38,31.88 25.4,31.88
NETSB21_1 on TOP (solid shape): 16.26,26.29 15.24,26.29 15.24,27.65 15.75,27.14 16.26,27.65
NETSB22_1 on TOP (solid shape): 17.78,26.29 16.76,26.29 16.76,27.65 17.27,27.14 17.78,27.65
NETSB26_2 on BOTTOM (solid shape): 91.19,19.78 90.68,19.27 90.17,19.78 90.17,20.7 91.19,20.7
NETSB27_2 on TOP (solid shape): 20.35,21.72 19.84,21.21 18.92,21.21 18.92,22.23 19.84,22.23
NETSB27_2 on BOTTOM (solid shape): 20.35,21.72 19.84,21.21 18.92,21.21 18.92,22.23 19.84,22.23
NETSB28_2 on TOP (solid shape): 20.35,23.11 19.84,22.61 18.92,22.61 18.92,23.62 19.84,23.62
NETSB28_2 on BOTTOM (solid shape): 20.35,23.11 19.84,22.61 18.92,22.61 18.92,23.62 19.84,23.62
NETSB33_2 on TOP (solid shape): 105.66,16.29 105.66,15.37 104.65,15.37 104.65,16.29 105.16,16.8
NETSB37_2 on TOP (solid shape): 74.2,10.16 73.69,9.65 72.77,9.65 72.77,10.67 73.69,10.67
NETSB48_1 on BOTTOM (solid shape): 30.35,32.67 29.84,33.18 29.34,32.67 29.34,34.04 30.35,34.04
NETSB51_1 on TOP (solid shape): 96.01,51.82 94.65,51.82 95.16,52.32 94.65,52.83 96.01,52.83
NETSB52_1 on TOP (solid shape): 96.01,50.16 94.65,50.16 95.16,50.67 94.65,51.18 96.01,51.18
NETSB68_2 on TOP (solid shape): 102.93,56.36 102.42,55.85 101.5,55.85 101.5,56.87 102.42,56.87
NETSB69_2 on TOP (solid shape): 102.93,54.81 102.42,54.31 101.5,54.31 101.5,55.32 102.42,55.32
NETSB70_2 on TOP (solid shape): 12.7,23.09 11.78,23.09 11.27,23.6 11.78,24.1 12.7,24.1
NETSB71_2 on TOP (solid shape): 12.7,24.66 11.78,24.66 11.27,25.17 11.78,25.68 12.7,25.68
PORT1_CC1 on TOP (solid shape): 90.42,40.01 89.06,40.01 89.57,40.51 89.06,41.02 90.42,41.02
PORT1_CC2 on TOP (solid shape): 93.6,40.01 92.24,40.01 92.74,40.51 92.23,41.02 93.6,41.02
PORT2_CC1 on TOP (solid shape): 94.9,50.67 94.39,50.16 93.47,50.16 93.47,51.18 94.39,51.18
PORT2_CC1 on BOTTOM (solid shape): 100.97,44.1 100.97,43.18 99.95,43.18 99.95,44.1 100.46,44.61
PORT2_CC2 on TOP (solid shape): 94.9,52.32 94.39,51.82 93.47,51.82 93.47,52.83 94.39,52.83
PORT2_CC2 on BOTTOM (solid shape): 102.36,44.1 102.36,43.18 101.35,43.18 101.35,44.1 101.85,44.61
PSU on TOP (solid shape): 105.66,16.55 105.16,17.05 104.65,16.54 104.65,17.91 105.66,17.91
PSU on TOP: 54.1,60.83 56.39,58.55 56.39,52.2 53.97,49.78 48.26,49.78 47.37,50.67 47.37,61.21 50.93,64.77 52.2,64.77 54.1,62.87
PSU on TOP: 105.92,9.14 107.19,9.14 107.38,8.95 107.38,7.24 108.33,6.29 108.33,5.21 108.84,4.7 108.84,1.78 108.58,1.52 105.54,1.52 105.16,1.91 105.16,3.81 105.92,4.57
PSU on TOP: 80.14,18.8 79.76,19.18 79.76,21.72 79.25,22.23 79.25,24 78.87,24.38 78.11,24.38 77.72,24 77.72,22.23 77.47,21.97 77.47,13.84 77.72,13.59 84.71,13.59 84.96,13.84 84.96,17.02 84.33,17.65 81.79,17.65 81.53,17.91 81.53,18.8
PSU on BOTTOM: 26.8,12.06 23.75,12.06 23.24,11.56 23.24,5.84 23.62,5.46 24.51,5.46 25.27,4.7 27.05,4.7 27.3,4.95 27.3,11.56
PSU on L3_SIG: 107.95,0.64 77.98,0.64 75.82,2.79 75.82,17.27 76.58,18.03 81.53,18.03 84.2,15.37 84.2,11.94 85.34,10.79 95.5,10.79 96.01,11.3 100.33,11.3 101.35,12.32 107.82,12.32 108.33,11.81 108.33,1.02
PSU on L4_VCC: 40.51,21.21 39.88,20.57 39.88,10.79 38.1,9.02 28.83,9.02 27.3,7.49 27.3,5.21 26.86,4.76 25.34,4.76 24.38,5.71 24.38,10.03 28.96,14.61 28.96,20.19 38.99,30.23 38.99,57.93 40.11,59.05 56.28,59.05 57.53,57.81 57.53,51.03 55.12,48.62 55.12,36.47 62.89,28.7 80.14,28.7 87.12,21.72 87.12,12.06 58.55,12.06 49.4,21.21
PWM_CTL on BOTTOM (solid shape): 94.23,19.08 94.23,18.16 93.22,18.16 93.22,19.08 93.73,19.59
V_CTL1 on BOTTOM (solid shape): 93.73,22.19 94.23,22.7 94.23,21.34 93.22,21.34 93.22,22.7
V_CTL1 on BOTTOM (solid shape): 94.23,19.34 93.72,19.85 93.22,19.34 93.22,20.7 94.23,20.7
V_CTL2 on BOTTOM (solid shape): 92.2,22.19 92.71,22.7 92.71,21.34 91.69,21.34 91.69,22.7
V_CTL2 on BOTTOM (solid shape): 92.71,19.34 92.2,19.85 91.69,19.34 91.69,20.7 92.71,20.7
VCONN_EN1 on TOP (solid shape): 89.12,35.44 89.63,34.92 88.27,34.92 88.27,35.94 89.63,35.94
VCONN_EN2 on TOP (solid shape): 92.3,35.44 92.81,34.92 91.44,34.92 91.44,35.94 92.8,35.94
VCONN_OUT on TOP (solid shape): 93.98,33.27 92.62,33.27 93.12,33.78 92.61,34.29 93.98,34.29
VCONN_OUT on TOP: 101.73,25.27 101.09,25.91 101.09,31.11 101.6,31.62 103.89,31.62 104.8,32.54 104.8,35.88 105.03,36.11 109.69,36.11 112.78,33.02 112.78,25.65 112.39,25.27
VDC on TOP (solid shape): 75.31,9.65 73.95,9.65 74.46,10.16 73.95,10.67 75.31,10.67
VDC on TOP: 66.67,6.86 66.93,7.11 66.93,8.38 66.8,8.51 62.61,8.51 62.36,8.76 56.9,8.76 56.52,8.38 56.52,5.97 56.77,5.71 62.99,5.71 63.12,5.84 63.12,6.48 63.5,6.86
VDC on BOTTOM: 58.93,12.95 58.93,5.97 58.42,5.46 56.39,5.46 55.88,5.97 55.88,10.79 55.12,11.56 50.55,11.56 50.16,11.94 50.16,13.59 50.67,14.1 57.78,14.1
VSOURCE on TOP (solid shape): 49.05,32.16 47.32,32.16 47.32,34.39 49.05,34.39
VSOURCE on TOP: 64.01,25.78 64.01,17.14 63.63,16.76 56.13,16.76 55.5,17.4 55.5,30.35 54.61,31.24 47.62,31.24 47.24,31.62 47.24,34.54 47.75,35.05 56.18,35.05 59.05,32.18 59.05,24.51 59.31,24.26 59.94,24.26 60.2,24.51 60.2,34.87 60.64,35.32 64,35.32 64.39,34.92 64.39,26.16
VSOURCE on BOTTOM: 60.33,24.13 63.88,24.13 64.01,24 64.01,17.14 63.63,16.76 60.45,16.76 59.94,17.27 59.94,23.75
VSOURCE_9V on BOTTOM (solid shape): 94.23,22.96 93.73,22.45 93.22,22.96 93.22,23.88 94.23,23.88
VSOURCE_15V on BOTTOM (solid shape): 92.71,22.96 92.2,22.45 91.69,22.96 91.69,23.88 92.71,23.88

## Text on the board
Ref Des/Silkscreen Bottom: COMPLIANT | 2002/95/EC | ON | OFF | PWM Mode | GPIO Mode | B | C
User.Comments: CR_UNNAMED_1
Ref Des/Silkscreen Top: DISPLAY_PORT_IN | PORT1_DRP | GND | DP_PWR_SINK | A | PORT1_MUX | PSU | VDC_SEL | DC_PWR | REDRIVER | PORT2_MUX | VBUS_SEL | +5V | DISABLE | ENABLE | DB2 | VCONN | DB1 | D5V | USB | USB3 | VBUS1 | LOAD | LOCAL_PWR1 | DC_IN | CAD_SNK | VBUS2_LOAD | VBUS2 | PORT2 | PORT1 | DISPLAY_PORT_OUT | DP_PWR_SOURCE | PORT2_SINK | S | C | MB1352C
User.23: 3 | 1,6 | 4.0 | 5.1 | 4.1 | 9.9 | 10.9 | N/A | 100 OHM | +/-10%
User.32: U1
User.40: FIGURE | SIZE | 8.0 | 10.0 | 12.0 | 15.0 | 29.0 | 36.0 | 40.0 | 43.0 | 48.0 | 51.0 | 80.0 | 59.0 | 138.0 | 47.0x24.0 | 57.0x24.0 | 67.0x24.0 | 67.0x28.0 | 87.0x28.0 | 87.0x40.0 | DRILL CHART: TOP to BOTTOM | ALL UNITS ARE IN MILS | TOLERANCE | +3.0/-3.0 | +2.0/-2.0 | +5.0/-5.0 | PLATED | NON-PLATED | QTY | 12 | 174 | 420 | 28 | 5 | 36 | 22 | 4 | 6 | 2 | 3 | 8
